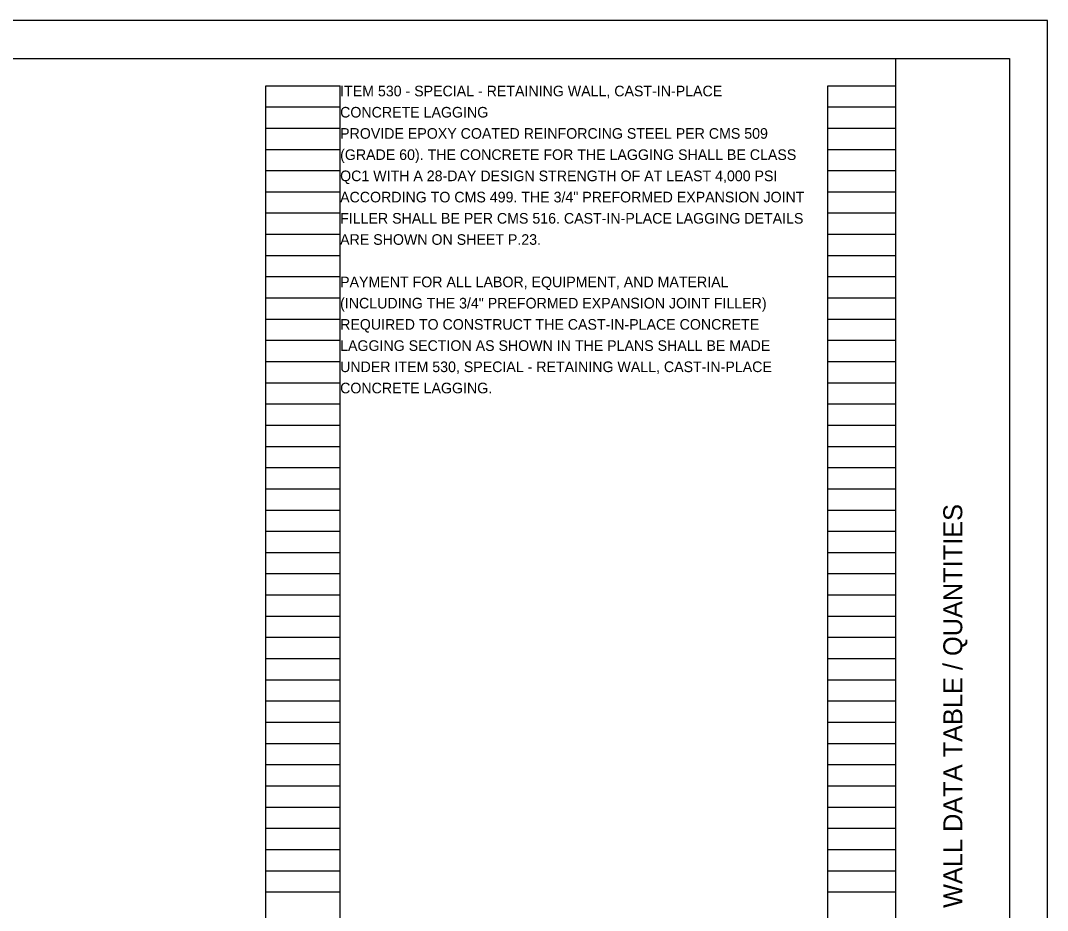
# Model space of a CAD drawing. Extents: x 0 to 34, y 0 to 22.
# Drawn here: x 20.44 to 34, y 10.25 to 22 of the extents above; entities that cross this region are included whole.
import ezdxf

# ---------------------------------------------------------------- set-up
doc = ezdxf.new("R2010")
doc.units = 0
for name, color, linetype in [('RD_P_Text', 7, 'Continuous'), ('SC_Scratch2', 7, 'Continuous'), ('SH_Border', 7, 'Continuous'), ('SH_Cut_Line', 7, 'Continuous'), ('SH_Data', 7, 'Continuous')]:
    doc.layers.add(name, color=color, linetype=linetype)

msp = doc.modelspace()

# ---------------------------------------------------------------- linework, layer by layer
at = {"layer": 'SC_Scratch2'}
for p, q in [((23.68, 0.98), (23.68, 21.14)), ((23.68, 21.14), (24.66, 21.14)), ((24.66, 0.98), (24.66, 21.14)), ((31.1, 0.98), (31.1, 21.14)), ((31.1, 21.14), (32, 21.14)), ((32, 0.98), (32, 21.14)), ((23.68, 20.86), (24.66, 20.86)), ((31.1, 20.86), (32, 20.86)), ((23.68, 20.58), (24.66, 20.58)), ((31.1, 20.58), (32, 20.58)), ((23.68, 20.3), (24.66, 20.3)), ((31.1, 20.3), (32, 20.3)), ((23.68, 20.02), (24.66, 20.02)), ((31.1, 20.02), (32, 20.02)), ((23.68, 19.74), (24.66, 19.74)), ((31.1, 19.74), (32, 19.74)), ((23.68, 19.46), (24.66, 19.46)), ((31.1, 19.46), (32, 19.46)), ((23.68, 19.18), (24.66, 19.18)), ((31.1, 19.18), (32, 19.18)), ((23.68, 18.9), (24.66, 18.9)), ((31.1, 18.9), (32, 18.9)), ((23.68, 18.62), (24.66, 18.62)), ((31.1, 18.62), (32, 18.62)), ((23.68, 18.34), (24.66, 18.34)), ((31.1, 18.34), (32, 18.34)), ((23.68, 18.06), (24.66, 18.06)), ((31.1, 18.06), (32, 18.06)), ((23.68, 17.78), (24.66, 17.78)), ((31.1, 17.78), (32, 17.78)), ((23.68, 17.5), (24.66, 17.5)), ((31.1, 17.5), (32, 17.5)), ((23.68, 17.22), (24.66, 17.22)), ((31.1, 17.22), (32, 17.22)), ((23.68, 16.94), (24.66, 16.94)), ((31.1, 16.94), (32, 16.94)), ((23.68, 16.66), (24.66, 16.66)), ((31.1, 16.66), (32, 16.66)), ((23.68, 16.38), (24.66, 16.38)), ((31.1, 16.38), (32, 16.38)), ((23.68, 16.1), (24.66, 16.1)), ((31.1, 16.1), (32, 16.1)), ((23.68, 15.82), (24.66, 15.82)), ((31.1, 15.82), (32, 15.82)), ((23.68, 15.54), (24.66, 15.54)), ((31.1, 15.54), (32, 15.54)), ((23.68, 15.26), (24.66, 15.26)), ((31.1, 15.26), (32, 15.26)), ((23.68, 14.98), (24.66, 14.98)), ((31.1, 14.98), (32, 14.98)), ((23.68, 14.7), (24.66, 14.7)), ((31.1, 14.7), (32, 14.7)), ((23.68, 14.42), (24.66, 14.42)), ((31.1, 14.42), (32, 14.42)), ((23.68, 14.14), (24.66, 14.14)), ((31.1, 14.14), (32, 14.14)), ((23.68, 13.86), (24.66, 13.86)), ((31.1, 13.86), (32, 13.86)), ((23.68, 13.58), (24.66, 13.58)), ((31.1, 13.58), (32, 13.58)), ((23.68, 13.3), (24.66, 13.3)), ((31.1, 13.3), (32, 13.3)), ((23.68, 13.02), (24.66, 13.02)), ((31.1, 13.02), (32, 13.02)), ((23.68, 12.74), (24.66, 12.74)), ((31.1, 12.74), (32, 12.74)), ((23.68, 12.46), (24.66, 12.46)), ((31.1, 12.46), (32, 12.46)), ((23.68, 12.18), (24.66, 12.18)), ((31.1, 12.18), (32, 12.18)), ((23.68, 11.9), (24.66, 11.9)), ((31.1, 11.9), (32, 11.9)), ((23.68, 11.62), (24.66, 11.62)), ((31.1, 11.62), (32, 11.62)), ((23.68, 11.34), (24.66, 11.34)), ((31.1, 11.34), (32, 11.34)), ((23.68, 11.06), (24.66, 11.06)), ((31.1, 11.06), (32, 11.06)), ((23.68, 10.78), (24.66, 10.78)), ((31.1, 10.78), (32, 10.78)), ((23.68, 10.5), (24.66, 10.5)), ((31.1, 10.5), (32, 10.5))]:
    msp.add_line(p, q, dxfattribs=at)
at = {"layer": 'SH_Border'}
msp.add_line((32, 0.5), (32, 21.5), dxfattribs=at)
msp.add_lwpolyline([(1.5, 21.5), (33.5, 21.5), (33.5, 0.5), (1.5, 0.5)], close=True, dxfattribs=at)
at = {"layer": 'SH_Cut_Line'}
msp.add_lwpolyline([(0, 0), (34, 0), (34, 22), (0, 22)], close=True, dxfattribs=at)

# ---------------------------------------------------------------- texts
at = {"layer": 'RD_P_Text'}
for s, p in [('ITEM 530 - SPECIAL - RETAINING WALL, CAST-IN-PLACE ', (24.66, 21)), ('CONCRETE LAGGING', (24.66, 20.72)), ('PROVIDE EPOXY COATED REINFORCING STEEL PER CMS 509 ', (24.66, 20.44)), ('(GRADE 60). THE CONCRETE FOR THE LAGGING SHALL BE CLASS ', (24.66, 20.16)), ('QC1 WITH A 28-DAY DESIGN STRENGTH OF AT LEAST 4,000 PSI ', (24.66, 19.88)), ('ACCORDING TO CMS 499. THE 3/4" PREFORMED EXPANSION JOINT ', (24.66, 19.6)), ('FILLER SHALL BE PER CMS 516. CAST-IN-PLACE LAGGING DETAILS ', (24.66, 19.32)), ('ARE SHOWN ON SHEET P.23.', (24.66, 19.04)), ('PAYMENT FOR ALL LABOR, EQUIPMENT, AND MATERIAL ', (24.66, 18.48)), ('(INCLUDING THE 3/4" PREFORMED EXPANSION JOINT FILLER) ', (24.66, 18.2)), ('REQUIRED TO CONSTRUCT THE CAST-IN-PLACE CONCRETE ', (24.66, 17.92)), ('LAGGING SECTION AS SHOWN IN THE PLANS SHALL BE MADE ', (24.66, 17.64)), ('UNDER ITEM 530, SPECIAL - RETAINING WALL, CAST-IN-PLACE ', (24.66, 17.36)), ('CONCRETE LAGGING. ', (24.66, 17.08))]:
    msp.add_text(s, height=0.14, dxfattribs=at).set_placement(p)
at = {"layer": 'SH_Data'}
msp.add_text('WALL DATA TABLE / QUANTITIES', height=0.25, rotation=90, dxfattribs=at).set_placement((32.875, 10.288))

doc.saveas('drawing.dxf')
